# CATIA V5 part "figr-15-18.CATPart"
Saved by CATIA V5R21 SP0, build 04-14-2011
Part number: Part1
Bounding box of the stored display mesh (mm): x -46.56 to 46.56, y -38.965 to 25.965, z 0 to 40
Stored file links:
  D:\CATIA V5R21 E-RESOURCES\CATIA-V5R21\catia-v5r21-prt\c15-catia-v5r20-prt\c15-catia-v5r21-figr-15-18.CATPart
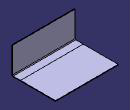
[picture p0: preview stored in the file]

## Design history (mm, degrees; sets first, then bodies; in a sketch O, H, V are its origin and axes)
SheetMetalParameters1: Thickness 1, BendRadius 1, KFactor 0.325257 {= log(min(100,max(20*SheetMetalParameters1.BendRadius,SheetMetalParameters1.Thickness)/SheetMetalParameters1.Thickness))/log(100)/2}, ReliefRadialLength 1, ReliefAxialLength 2, MinimumBendRadius 0
Body1 (main body)
  Sketch1 on xy-plane, origin (0, 0, 0), H (1, 0, 0), V (0, 1, 0)
    line L1 (-46.5596, 25.9646) -> (46.5596, 25.9646)
    line L2 (46.5596, 25.9646) -> (46.5596, -25.9646)
    line L3 (46.5596, -25.9646) -> (-46.5596, -25.9646)
    line L4 (-46.5596, -25.9646) -> (-46.5596, 25.9646)
    horizontal: L1 H, L3 H
    vertical: L2 V, L4 V
    symmetry: L1 L3 H, L4 L2 V
  Wall1: Thickness 1, Profile Sketch1
  d_NewWallOnEdge1: NewWallOnEdge_Edge edge [face of Wall1 | face of Wall1], NewWallOnEdge_Length 40, NewWallOnEdge_HeightLimitOffset 0, NewWallOnEdge_WidthOffset1 0, NewWallOnEdge_WidthOffset2 0, NewWallOnEdge_Angle 90, NewWallOnEdge_BendRadiusValue 1 {= SheetMetalParameters1.BendRadius}, NewWallOnEdge_BendTable SheetMetalParameters1, KFacteur 0.325257 {= log(min(100,max(20*d_NewWallOnEdge1.Radius,SheetMetalParameters1.Thickness)/SheetMetalParameters1.Thickness))/log(100)/2}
